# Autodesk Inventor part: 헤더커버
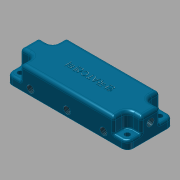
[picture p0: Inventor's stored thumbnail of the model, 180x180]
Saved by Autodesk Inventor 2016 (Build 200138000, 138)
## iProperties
Created: 2015-11
Part Number: 헤더커버
Material: 알루미늄 6061
Document SubType Name: Modeling
Designer: mduedu
Density: 2.71 g/cm^3
Appearance: 하늘색 짙음
Mass: 171.77 g
Surface Area: 160.864 cm^2
Volume: 63.3839 cm^3
Author: mduedu
## Parameters: d0 = 105 mm, d3 = 0, d4 = 12 mm, d5 = 12 mm, d6 = 13 mm, d7 = 0, d8 = 5 mm, d9 = 1 mm, d10 = 5 mm, d11 = 2 mm, d12 = 3 mm, d13 = 6 mm, d14 = 6 mm, d15 = 4.5 mm, d16 = 6 mm, d17 = 4 mm, d18 = 2 mm, d19 = 90 deg, d20 = 8 mm, d21 = 118 deg, d22 = 24.5 mm, d23 = 24.5 mm, d24 = 24.5 mm, d25 = 32 mm, d26 = 32 mm, d27 = 8 mm, d28 = 0, d29 = 5 mm, d32 = 120 deg, d34 = 12 mm, d35 = 8 mm, d38 = 12 mm, d39 = 120 deg, d40 = 8 mm, d43 = 5.944 mm, d44 = 6.886 mm, d45 = 0.62479 mm, d46 = 5.959 mm, d47 = 4 mm, d48 = 2 mm, d49 = 90 deg, d50 = 6.9 mm, d51 = 0, d54 = 5.944 mm, d55 = 6.886 mm, d56 = 0.62479 mm, d57 = 5.959 mm, d58 = 4 mm, d59 = 2 mm, d60 = 90 deg, d61 = 6.9 mm, d62 = 0, d65 = 5.944 mm, d66 = 6.886 mm, d67 = 0.62479 mm, d68 = 5.959 mm, d69 = 4 mm, d70 = 2 mm, d71 = 90 deg, d72 = 6.9 mm, d73 = 0, d74 = 0, d75 = 0, d76 = 0, d77 = 5 mm, d78 = 5.944 mm, d79 = 6.886 mm, d80 = 0.62479 mm, d81 = 5.959 mm, d82 = 4 mm, d83 = 2 mm, d84 = 90 deg, d85 = 6.9 mm, d86 = 0, d87 = 8 mm, d88 = 0, d89 = 0.5 mm, d90 = 0, d91 = 0, d92 = 0, d93 = 0
